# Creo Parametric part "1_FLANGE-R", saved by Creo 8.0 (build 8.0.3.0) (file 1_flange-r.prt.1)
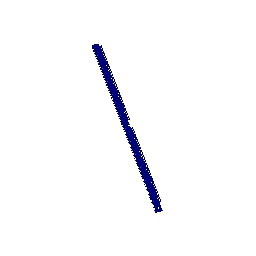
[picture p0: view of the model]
Units: millimeter Newton Second (mmNs); MM, TONNE, SECS

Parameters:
  SMT_DFLT_BEND_REL_LENGTH_TYPE = "Through All"

Other parameters: SMT_UPDATE_BEND_ALLOW_INFO, SMT_THICKNESS, SMT_PART_BEND_ALLOWANCE_FACTOR, SMT_DFLT_BEND_RADIUS, SMT_DFLT_BEND_ANGLE, SMT_DFLT_CRNR_REL_WIDTH, SMT_DFLT_CRNR_REL_DEPTH, SMT_DFLT_BEND_REL_WIDTH, SMT_DFLT_BEND_REL_DEPTH, SMT_DFLT_BEND_REL_LENGTH, SMT_DFLT_BEND_REL_ANGLE, SMT_GAP, SMT_DFLT_EDGE_TREA_WIDTH, SMT_DFLT_MITER_CUT_WIDTH, SMT_DFLT_MITER_CUT_OFFSET

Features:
  1. datum plane "RIGHT"
  2. datum plane "TOP"
  3. datum plane "FRONT"
  4. coordinate system
  5. pattern
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
Other named items: COPIED_GROUP, COPIED_GROUP_1, COPIED_GROUP_3

Layers: 0_ALL_AXIS, 0_ALL_CSYS, 0_ALL_CURVES, 0_ALL_PLANES, 0_ALL_POINTS, 0_ALL_SURFS, 1_FLANGE-R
